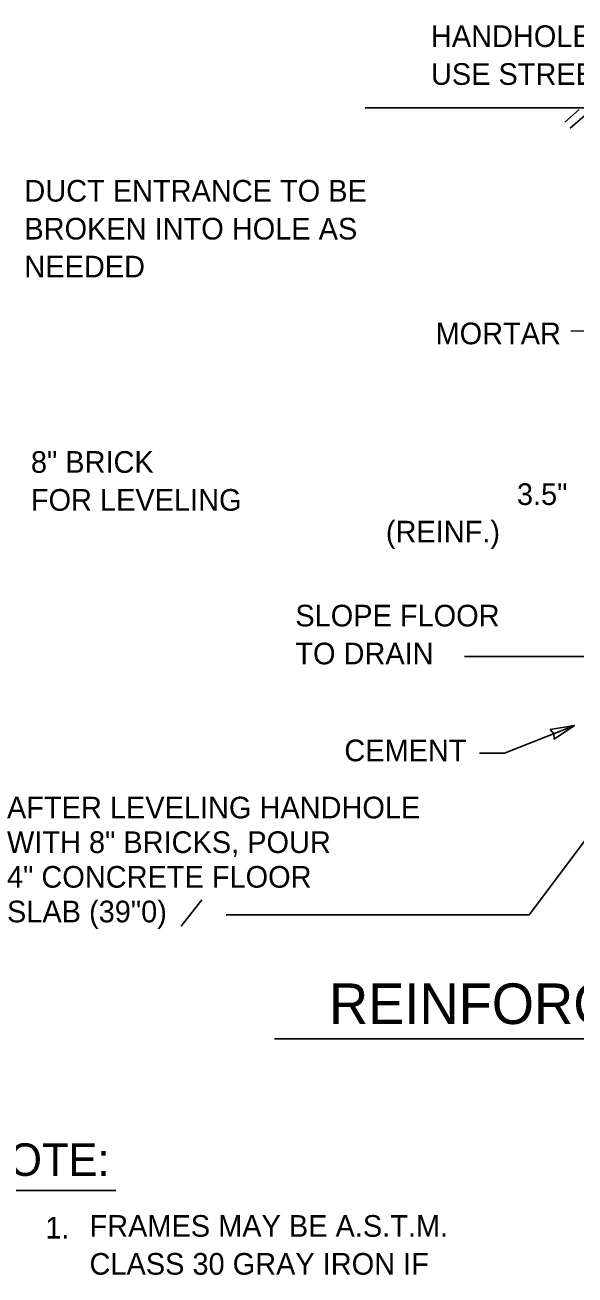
# Model space of a CAD drawing. Extents: x 19188 to 19495, y 20866 to 21061.
# Drawn here: x 19418.78 to 19440.07, y 21012.44 to 21060.79 of the extents above; entities that cross this region are included whole.
import ezdxf

# ---------------------------------------------------------------- set-up
doc = ezdxf.new("R2010")
doc.units = 0
doc.layers.add('G-ANNO-NOTE', color=7, linetype='Continuous')

msp = doc.modelspace()

# ---------------------------------------------------------------- linework, layer by layer
at = {"layer": 'G-ANNO-NOTE'}
for p, q in [((19445.138, 21057.586), (19431.945, 21057.586)), ((19440.235, 21057.514), (19439.682, 21057.029)), ((19440.75, 21057.549), (19439.889, 21056.793)), ((19435.796, 21036.355), (19446.658, 21036.355)), ((19437.348, 21032.62), (19440.049, 21033.687)), ((19440.049, 21033.687), (19439.256, 21033.374)), ((19436.371, 21032.62), (19437.348, 21032.62)), ((19424.82, 21025.929), (19425.625, 21026.942)), ((19428.442, 21021.575), (19478.142, 21021.575)), ((19415.838, 21015.7), (19422.298, 21015.7))]:
    msp.add_line(p, q, dxfattribs=at)
for points in [[(19444.907, 21052.068), (19440.852, 21048.956), (19439.916, 21048.938)], [(19439.255, 21033.374), (19439.111, 21033.536), (19440.049, 21033.687), (19439.26, 21033.166), (19439.255, 21033.374)], [(19426.568, 21026.367), (19438.302, 21026.367), (19443.319, 21033.045)]]:
    msp.add_lwpolyline(points, dxfattribs=at)

# ---------------------------------------------------------------- texts
for s, height, p in [('HANDHOLE FRAME & COVER', 0.83785, (19434.494, 21059.936)), ('USE STREET TYPE ONLY.', 0.83785, (19434.494, 21058.47)), ('DUCT ENTRANCE TO BE', 0.83785, (19418.754, 21053.955)), ('BROKEN INTO HOLE AS', 0.83785, (19418.754, 21052.489)), ('NEEDED', 0.8379, (19418.754, 21051.023)), ('MORTAR', 0.8379, (19434.672, 21048.437)), ('8" BRICK  ', 0.8379, (19419.006, 21043.465)), ('FOR LEVELING', 0.83785, (19419.006, 21041.998)), ('3.5"', 0.8379, (19437.823, 21042.22)), ('(REINF.)', 0.8379, (19432.749, 21040.77)), ('SLOPE FLOOR', 0.83785, (19429.244, 21037.522)), ('TO DRAIN', 0.8379, (19429.244, 21036.056)), ('CEMENT', 0.8379, (19431.141, 21032.308)), ('AFTER LEVELING HANDHOLE', 0.83785, (19418.081, 21030.099)), ('WITH 8" BRICKS, POUR ', 0.83785, (19418.081, 21028.759)), ('4" CONCRETE FLOOR', 0.83785, (19418.081, 21027.418)), ('SLAB (39"0)', 0.83785, (19418.081, 21026.077)), ('REINFORCED CONCRETE PIPE (CLASS III )', 1.57098, (19430.549, 21022.144)), ('NOTE:', 1.2568, (19416.915, 21016.271)), ('1.', 0.8379, (19419.565, 21013.848)), ('FRAMES MAY BE A.S.T.M.', 0.83785, (19421.275, 21013.915)), ('CLASS 30 GRAY IRON IF', 0.83785, (19421.275, 21012.448))]:
    msp.add_text(s, height=height, dxfattribs=at).set_placement(p)

doc.saveas('drawing.dxf')
